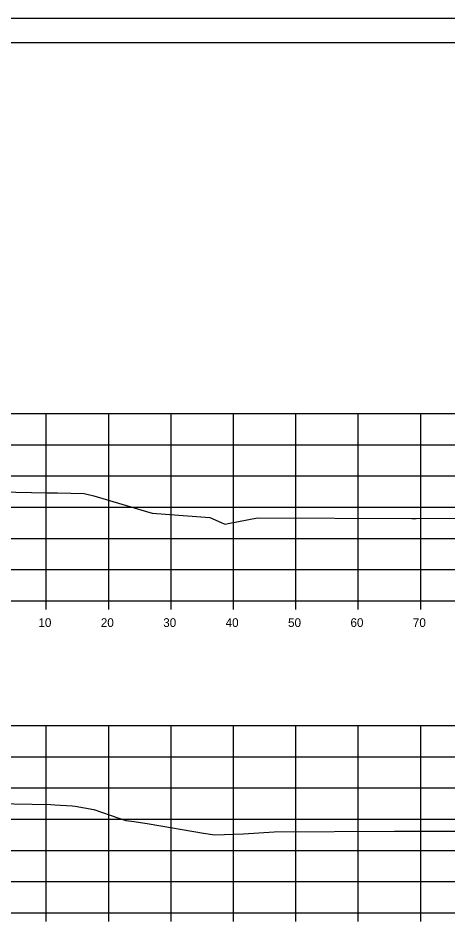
# Model space of a CAD drawing. Extents: x 1368503 to 1373085, y 379840 to 381833.
# Drawn here: x 1368678.6 to 1368747.4, y 379980.6 to 380126 of the extents above; entities that cross this region are included whole.
import ezdxf

# ---------------------------------------------------------------- set-up
doc = ezdxf.new("R2010")
doc.units = 0
for name, color, linetype in [('S_BRIDGE', 7, 'Continuous'), ('S_EDGE_PAVEMENT', 7, 'Continuous'), ('S_MISC_BOUNDARY', 7, 'Continuous'), ('S_PHOTO_CENTERS', 7, 'Continuous'), ('S_PHOTO_NOTES', 7, 'Continuous'), ('S_TRAILS', 7, 'Continuous')]:
    doc.layers.add(name, color=color, linetype=linetype)

msp = doc.modelspace()

# ---------------------------------------------------------------- linework, layer by layer
at = {"layer": 'S_BRIDGE'}
msp.add_line((1368515.06, 380122.15), (1368831.24, 380122.15), dxfattribs=at)
at = {"layer": 'S_EDGE_PAVEMENT'}
for p, q in [((1368533.06, 380032.69), (1368813.06, 380032.69)), ((1368683.06, 380031.29), (1368683.06, 380032.69)), ((1368693.06, 380031.29), (1368693.06, 380032.69)), ((1368703.06, 380031.29), (1368703.06, 380032.69)), ((1368713.06, 380031.29), (1368713.06, 380032.69)), ((1368723.06, 380031.29), (1368723.06, 380032.69)), ((1368733.06, 380031.29), (1368733.06, 380032.69)), ((1368743.06, 380031.29), (1368743.06, 380032.69)), ((1368533.06, 379982.69), (1368813.06, 379982.69)), ((1368683.06, 379981.29), (1368683.06, 379982.69)), ((1368693.06, 379981.29), (1368693.06, 379982.69)), ((1368703.06, 379981.29), (1368703.06, 379982.69)), ((1368713.06, 379981.29), (1368713.06, 379982.69)), ((1368723.06, 379981.29), (1368723.06, 379982.69)), ((1368733.06, 379981.29), (1368733.06, 379982.69)), ((1368743.06, 379981.29), (1368743.06, 379982.69))]:
    msp.add_line(p, q, dxfattribs=at)
at = {"layer": 'S_MISC_BOUNDARY'}
for points in [[(1368673.13, 380050.19), (1368683.23, 380050), (1368683.6, 380049.99), (1368683.91, 380049.99), (1368684.85, 380049.97), (1368689.11, 380049.87), (1368690.68, 380049.53), (1368699.67, 380046.82), (1368699.85, 380046.77), (1368700.03, 380046.75), (1368709.25, 380046.04), (1368711.07, 380045.25), (1368711.58, 380045.03), (1368711.71, 380044.97), (1368712.19, 380045.06), (1368716.89, 380045.98), (1368741.65, 380045.88), (1368741.78, 380045.88), (1368741.81, 380045.88), (1368742.32, 380045.88), (1368754.95, 380045.93)], [(1368674.81, 380000.23), (1368683.78, 380000.03), (1368684.46, 380000), (1368687.23, 379999.84), (1368687.68, 379999.77), (1368690.68, 379999.25), (1368694.7, 379997.85), (1368695.82, 379997.47), (1368697.14, 379997.3), (1368699.56, 379996.94), (1368708.28, 379995.46), (1368710.09, 379995.19), (1368714.67, 379995.36), (1368719.59, 379995.64), (1368738.86, 379995.78), (1368742.58, 379995.75), (1368761.43, 379995.79)]]:
    msp.add_lwpolyline(points, dxfattribs=at)
at = {"layer": 'S_PHOTO_CENTERS'}
for p, q in [((1368533.06, 380062.69), (1368813.06, 380062.69)), ((1368683.06, 380032.69), (1368683.06, 380062.69)), ((1368693.06, 380032.69), (1368693.06, 380062.69)), ((1368703.06, 380032.69), (1368703.06, 380062.69)), ((1368713.06, 380032.69), (1368713.06, 380062.69)), ((1368723.06, 380032.69), (1368723.06, 380062.69)), ((1368733.06, 380032.69), (1368733.06, 380062.69)), ((1368743.06, 380032.69), (1368743.06, 380062.69)), ((1368533.06, 380057.69), (1368813.06, 380057.69)), ((1368533.06, 380052.69), (1368813.06, 380052.69)), ((1368533.06, 380047.69), (1368813.06, 380047.69)), ((1368533.06, 380042.69), (1368813.06, 380042.69)), ((1368533.06, 380037.69), (1368813.06, 380037.69)), ((1368533.06, 380032.69), (1368813.06, 380032.69)), ((1368533.06, 380012.69), (1368813.06, 380012.69)), ((1368683.06, 379982.69), (1368683.06, 380012.69)), ((1368693.06, 379982.69), (1368693.06, 380012.69)), ((1368703.06, 379982.69), (1368703.06, 380012.69)), ((1368713.06, 379982.69), (1368713.06, 380012.69)), ((1368723.06, 379982.69), (1368723.06, 380012.69)), ((1368733.06, 379982.69), (1368733.06, 380012.69)), ((1368743.06, 379982.69), (1368743.06, 380012.69)), ((1368533.06, 380007.69), (1368813.06, 380007.69)), ((1368533.06, 380002.69), (1368813.06, 380002.69)), ((1368533.06, 379997.69), (1368813.06, 379997.69)), ((1368533.06, 379992.69), (1368813.06, 379992.69)), ((1368533.06, 379987.69), (1368813.06, 379987.69)), ((1368533.06, 379982.69), (1368813.06, 379982.69))]:
    msp.add_line(p, q, dxfattribs=at)
at = {"layer": 'S_PHOTO_NOTES'}
msp.add_line((1368502.66, 380126.04), (1368835.99, 380126.04), dxfattribs=at)
for points in [[(1368502.65, 380126.04), (1368835.99, 380126.04), (1368835.99, 379912.71), (1368502.65, 379912.71)], [(1368748.98, 380122.15), (1368748.98, 380112.27), (1368784.71, 380112.27), (1368784.71, 380109.35), (1368807.91, 380109.35), (1368807.91, 380085.02), (1368831.24, 380085.02), (1368831.24, 379916.69), (1368515.06, 379916.69), (1368515.06, 380122.15)]]:
    msp.add_lwpolyline(points, close=True, dxfattribs=at)

# ---------------------------------------------------------------- texts
at = {"layer": 'S_TRAILS'}
for s, p in [('10', (1368681.8, 380028.49)), ('20', (1368691.8, 380028.49)), ('30', (1368701.8, 380028.49)), ('40', (1368711.8, 380028.49)), ('50', (1368721.8, 380028.49)), ('60', (1368731.8, 380028.49)), ('70', (1368741.8, 380028.49))]:
    msp.add_text(s, height=1.4, dxfattribs=at).set_placement(p)

doc.saveas('drawing.dxf')
